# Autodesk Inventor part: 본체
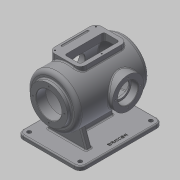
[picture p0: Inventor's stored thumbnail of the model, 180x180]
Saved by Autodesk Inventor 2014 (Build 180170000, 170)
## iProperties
Created: 2016-02
Part Number: 본체
Material: 일반
Document SubType Name: Modeling
Designer: mduedu
Density: 2.71 g/cm^3
Appearance: 기본값
Author: mduedu
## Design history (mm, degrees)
sketch "스케치2"
  geometry: L1 (0, 100)-(0, -100); L2 (65, -75.993)-(65, 100); L3 (65, 100)-(0, 100); A1 r 100 centre (0, 0) between (0, -100) and (65, -75.993); 2 further points
  constraints: 6 end point, 2 midpoint, 2 point on circle, 1 centre point, 1 coincident, 1 horizontal, 1 parallel, 1 vertical
  dimensions: "d3" = 200 distance of L1.start L1.end; "d5" = 130 diameter of L2 L1; "d6" = 100 radius of A1
revolve "회전1" sketch "스케치2" stored, may be unused: angle "d7" = 90 deg
sketch "스케치3"
  geometry: C1 r 47.5 at (0, 0); 1 further point
  constraints: 1 centre point, 1 coincident
  dimensions: "d8" = 95 diameter of C1
extrude "돌출2" join sketch "스케치3" distance "d10" = 10; taper "d11" = 0 deg
sketch "스케치5"
  geometry: L1 (47.5, 110)-(47.5, 100) reference; L2 (47.5, 100)-(65, 100) reference; L3 (65, 100)-(65, -75.993) reference; L4 (-65, -75.993)-(-65, 100) reference; L5 (-65, 100)-(-47.5, 100) reference; L6 (-47.5, 100)-(-47.5, 110) reference; L7 (-47.5, 110)-(47.5, 110) reference; L8 (55, 85)-(55, -71.239); L9 (0, 85)-(55, 85); L10 (0, 85)-(0, -90); A1 r 100 centre (0, 0) between (0, -100) and (65, -75.993) reference; A2 r 100 centre (0, 0) between (-65, -75.993) and (0, -100) reference; A3 r 90 centre (0, 0) between (0, -90) and (55, -71.239); 1 further point
  constraints: 6 end point, 2 point on circle, 1 centre point, 1 parallel, 1 perpendicular, 1 point on line, 1 vertical
  dimensions: "d13" = 10 distance between parallel lines of L3 L8; "d14" = 10 radial gap between concentric circles of A3 A1; "d15" = 15 distance between parallel lines of L9 L2
revolve "회전2" sketch "스케치5" stored, may be unused: angle "d16" = 90 deg
hole "구멍1" diameter "d19" = 65; stored, may be unused: countersink angle "d23" = 90 deg, drill point angle "d25" = 118 deg; dims "d17" = 10, "d18" = 10, "d20" = 6, "d21" = 4, "d22" = 2, "d24" = 8
node "작업 평면1"
sketch "스케치6"
  geometry: L1 (47.5, 110)-(-47.5, 110) reference; C1 r 40 at (0, -17); 1 further point
  constraints: 1 centre point, 1 vertical alignment
  dimensions: "d27" = 80 diameter of C1; "d29" = 127 distance from line of C1.centre L1
extrude "돌출3" join sketch "스케치6" stored distance "d30" = 10; taper "d31" = 0 deg
hole "구멍2" diameter "d34" = 42; stored, may be unused: countersink angle "d38" = 90 deg, drill point angle "d40" = 118 deg; dims "d32" = 10, "d33" = 10, "d35" = 6, "d36" = 52, "d37" = 18, "d39" = 8
sketch "스케치7" dims "d41" = 65
  geometry: C1 r 40 at (0, 0) reference; 3 further points
  constraints: 2 vertical alignment, 1 coincident, 2 other
hole "구멍3" sketch "스케치7" at (0, 32.5) diameter "d43" = 3.242; stored, may be unused: countersink angle "d47" = 90 deg, drill point angle "d49" = 118 deg; dims "d44" = 11, "d45" = 13, "d46" = 18, "d48" = 13
sketch "스케치8" dims "d53" = 80
  geometry: 3 further points
  constraints: 2 vertical alignment, 1 coincident, 2 other
hole "구멍4" sketch "스케치8" at (0, 40) diameter "d56" = 3.242; stored, may be unused: countersink angle "d60" = 90 deg, drill point angle "d62" = 118 deg; dims "d57" = 11, "d58" = 13, "d59" = 18, "d61" = 13
fillet "모깎기1" dims "d66" = 10
fillet "모깎기2" dims "d67" = 3
fillet "모깎기3" dims "d68" = 0.3
chamfer "모따기1" distance "d69" = 1; stored, may be unused: second distance "d70" = 2, angle "d71" = 45 deg
node "작업 평면5"
sketch "스케치10"
  geometry: L1 (-50, 0)-(50, 0); L2 (-50, 64)-(50, 64); L3 (50, 64)-(50, 50); L4 (50, 50)-(-50, 50); L5 (-50, 50)-(-50, 64); 3 further points
  constraints: 10 end point, 2 horizontal, 2 midpoint, 2 vertical, 1 coincident, 1 vertical alignment
  dimensions: "d132" = 100 distance of L1.start L1.end; "d158" = 50 distance between parallel lines of L4 L1; "d159" = 14 distance of L2.end L3.end; "d160" = 100 distance of L2.start L2.end
extrude "돌출5" join sketch "스케치10" stored distance "d84" = 10; taper "d85" = 0 deg
feature "면 기울기3" dims angle "d135" = 20 deg
sketch "스케치11"
  geometry: L1 (-100, 64)-(-100, 50) reference; L2 (-100, 50)-(-100, -50); L3 (-65, 90)-(-65, -71.239) reference; L4 (-100, -50)-(-65, -50); L5 (-100, 50)-(-55.515, 50) reference; 1 further point
  constraints: 4 end point, 1 collinear, 1 perpendicular, 1 point on line
  dimensions: "d161" = 100 distance between parallel lines of L4 L5
feature "리브1" sketch "스케치11" dims "d88" = 1, "d89" = 8, "d90" = 0, "d91" = 0, "d92" = 1, "d93" = 1
fillet "모깎기5" dims "d103" = 3
fillet "모깎기6" dims "d105" = 3
node "작업 평면6"
sketch "스케치15"
  geometry: L1 (-30, 60)-(50, 60); L2 (50, 60)-(50, -60); L3 (50, -60)-(-30, -60); L4 (-30, -60)-(-30, 60); 3 further points
  constraints: 8 end point, 2 parallel, 1 horizontal, 1 horizontal alignment, 1 midpoint, 1 perpendicular, 1 vertical alignment
  dimensions: "d110" = 80 distance of L2.end L3.end; "d112" = 60 distance from line of L3 point (10, 0); "d113" = 120 distance of L1.end L2.end; "d149" = 30 distance from line of L4 point (0, 0)
extrude "돌출8" join sketch "스케치15" stored distance "d114" = 10; taper "d115" = 0 deg
fillet "모깎기7" dims "d116" = 15
sketch "스케치16"
  geometry: L1 (-30, -45)-(-30, 45) reference; L2 (-15, 60)-(35, 60) reference; L3 (35, -60)-(-15, -60) reference; L4 (-20, -45)-(-20, 45); L5 (-15, 50)-(15, 50); L6 (20, 45)-(20, -45); L7 (15, -50)-(-15, -50); L8 (50, 45)-(50, -45) reference; A1 r 15 centre (-15, -45) between (-30, -45) and (-15, -60) reference; A2 r 15 centre (-15, 45) between (-15, 60) and (-30, 45) reference; A3 r 5 centre (-15, -45) between (-20, -45) and (-15, -50); A4 r 5 centre (-15, 45) between (-15, 50) and (-20, 45); A5 r 5 centre (15, 45) between (20, 45) and (15, 50); A6 r 5 centre (15, -45) between (15, -50) and (20, -45); A7 r 15 centre (35, 45) between (50, 45) and (35, 60) reference; A8 r 15 centre (35, -45) between (35, -60) and (50, -45) reference
  constraints: 8 end point, 8 point on circle, 4 centre point, 2 equal radius, 3 other
  dimensions: "d137" = 10 distance between parallel lines of L4 L1; "d150" = 40 distance between parallel lines of L6 L4; "d151" = 100 distance between parallel lines of L7 L5
extrude "돌출9" cut sketch "스케치16" stored distance "d118" = 10; taper "d119" = 0 deg
fillet "모깎기8" dims "d120" = 3
sketch "스케치17"
  geometry: L1 (-30, -45)-(-30, 45) reference; L2 (-20, 45)-(-20, -45) reference; L3 (-15, -50)-(15, -50) reference; L4 (20, -45)-(20, 45) reference; L5 (15, 50)-(-15, 50) reference; L6 (-15, 60)-(35, 60) reference; L7 (35, -60)-(-15, -60) reference; L8 (15, 55)-(-15, 55); L9 (-25, 45)-(-25, -45); L10 (-15, -55)-(15, -55); L11 (25, -45)-(25, 45); L12 (50, 45)-(50, -45) reference; L13 (35, 55)-(-15, 55); L14 (-25, 45)-(-25, -45); L15 (-15, -55)-(35, -55); L16 (45, -45)-(45, 45); A1 r 5 centre (-15, 45) between (-15, 50) and (-20, 45) reference; A2 r 5 centre (-15, -45) between (-20, -45) and (-15, -50) reference; A3 r 5 centre (15, -45) between (15, -50) and (20, -45) reference; A4 r 5 centre (15, 45) between (20, 45) and (15, 50) reference; A5 r 15 centre (-15, 45) between (-15, 60) and (-30, 45) reference; A6 r 15 centre (-15, -45) between (-30, -45) and (-15, -60) reference; A7 r 10 centre (-15, 45) between (-15, 55) and (-25, 45); A8 r 10 centre (-15, -45) between (-25, -45) and (-15, -55); A9 r 10 centre (15, -45) between (15, -55) and (25, -45); A10 r 10 centre (15, 45) between (25, 45) and (15, 55); A11 r 15 centre (35, 45) between (50, 45) and (35, 60) reference; A12 r 15 centre (35, -45) between (35, -60) and (50, -45) reference; A13 r 10 centre (-15, 45) between (-15, 55) and (-25, 45); A14 r 10 centre (-15, -45) between (-25, -45) and (-15, -55); A15 r 10 centre (35, -45) between (35, -55) and (45, -45); A16 r 10 centre (35, 45) between (45, 45) and (35, 55); 6 further points
  constraints: 18 point on circle, 16 end point, 8 centre point, 4 midpoint, 4 tangent, 11 other
  dimensions: "d138" = 5 distance between parallel lines of L8 L6; "d157" = 5 distance between parallel lines of L12 L16
hole "구멍5" sketch "스케치17" at (-25, 0), (42.071, 52.071), (42.071, -52.071) diameter "d122" = 3.242; stored, may be unused: countersink angle "d126" = 90 deg, drill point angle "d128" = 118 deg; dims "d123" = 9, "d124" = 13, "d125" = 18, "d127" = 11
sketch "스케치19"
  geometry: L1 (-50, 70)-(-35, 70) reference; L2 (-50, 42.603)-(-50, 70) reference; C1 r 2.5 at (-43, 70); 1 further point
  constraints: 1 centre point, 1 point on line
  dimensions: "d152" = 5 diameter of C1; "d153" = 7 distance from line of C1.centre L2
extrude "돌출11" cut sketch "스케치19" stored distance "d154" = 70; taper "d155" = 0 deg
fillet "모깎기11" dims "d156" = 2.5
sketch "스케치20"
  geometry: L1 (-80, 110)-(80, 110); L2 (80, 110)-(80, -100); L3 (80, -100)-(-80, -100); L4 (-80, -100)-(-80, 110); 2 further points
  constraints: 8 end point, 2 parallel, 1 horizontal, 1 midpoint, 1 perpendicular, 1 vertical alignment
  dimensions: "d162" = 160 distance of L1.start L1.end; "d164" = 210 distance of L1.end L2.end; "d165" = 110 distance from line of L1 point (0, 0)
extrude "돌출12" join sketch "스케치20" distance "d166" = 10; taper "d167" = 0 deg
fillet "모깎기12" dims "d168" = 15
fillet "모깎기13" dims "d169" = 3
fillet "모깎기14" dims "d170" = 3
sketch "스케치21"
  geometry: C1 r 5 at (-65, -95); C2 r 5 at (65, -95); C3 r 5 at (65, 85); C4 r 5 at (-65, 85); A1 r 15 centre (-65, -95) between (-80, -95) and (-65, -110) reference; A2 r 15 centre (-65, 85) between (-65, 100) and (-80, 85) reference; A3 r 15 centre (65, 85) between (80, 85) and (65, 100) reference; A4 r 15 centre (65, -95) between (65, -110) and (80, -95) reference; 1 further point
  constraints: 4 centre point, 4 coincident, 3 equal radius
  dimensions: "d171" = 10 diameter of C1
extrude "돌출13" cut sketch "스케치21" stored distance "d172" = 10; taper "d173" = 0 deg
sketch "스케치22"
  geometry: L1 (80, -95)-(80, 85) reference; 2 further points
  constraints: 1 horizontal alignment, 1 other
  dimensions: "d174" = 15 distance from line of L1 point (65, 0)
feature "엠보싱2" sketch "스케치22" dims "d13" = 10, "d175" = 0.5, "d176" = 0
node "솔리드2"
pattern_circular "원형 패턴1" dims angle "d51" = 360 deg
mirror "대칭1"
pattern_circular "원형 패턴2" dims angle "d64" = 360 deg
node "절단 모서리 투영1"
node "절단 모서리 투영2"
node "절단 모서리 투영3"
other parameters: "d26" = 75
